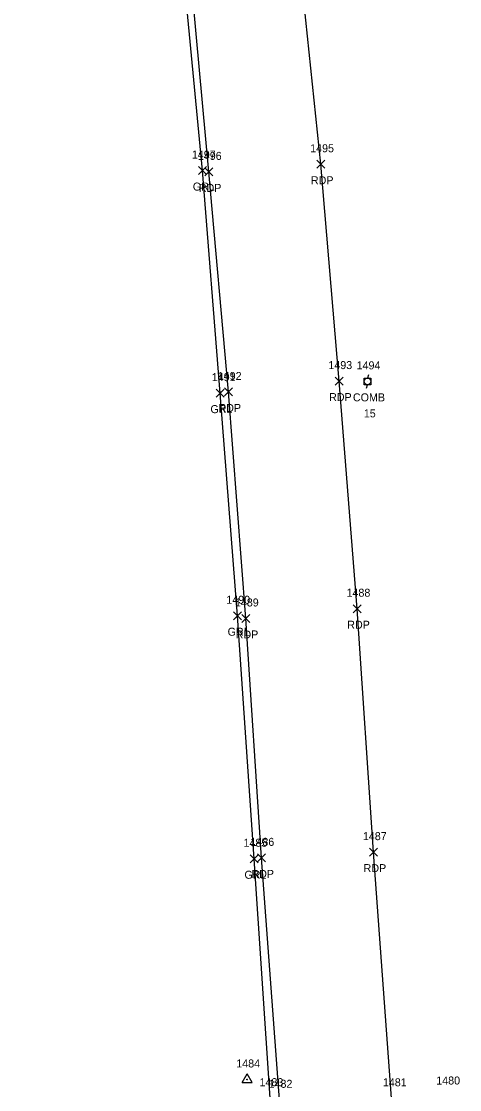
# Model space of a CAD drawing. Extents: x 1503463 to 1505240, y 712171 to 717196.
# Drawn here: x 1503465.6 to 1503575.2, y 716662.1 to 716929.1 of the extents above; entities that cross this region are included whole.
import ezdxf

# ---------------------------------------------------------------- set-up
doc = ezdxf.new("R2010")
doc.units = 0
for name, color, linetype in [('C_I', 7, 'Continuous'), ('CPH', 7, 'Continuous'), ('L_I', 7, 'Continuous'), ('P_A', 7, 'Continuous'), ('P_I', 7, 'Continuous'), ('P_TIC', 7, 'Continuous'), ('PET', 7, 'Continuous'), ('R_A', 7, 'Continuous'), ('R_I', 7, 'Continuous'), ('R_TIC', 7, 'Continuous'), ('RGR', 7, 'Continuous'), ('U_A', 7, 'Continuous'), ('U_C', 7, 'Continuous'), ('U_I', 7, 'Continuous'), ('UP', 7, 'Continuous')]:
    doc.layers.add(name, color=color, linetype=linetype)

msp = doc.modelspace()

# ---------------------------------------------------------------- linework, layer by layer
at = {"layer": 'CPH'}
for p, q in [((1503520.77, 716663.94), (1503522.02, 716666.1)), ((1503523.27, 716663.94), (1503522.02, 716666.1)), ((1503520.77, 716663.94), (1503523.27, 716663.94)), ((1503522.02, 716664.66), (1503522.02, 716664.66))]:
    msp.add_line(p, q, dxfattribs=at)
msp.add_circle((1503522.02, 716664.66), 0.0833, dxfattribs=at)
at = {"layer": 'P_TIC'}
for points in [[(1503539.5, 716892.37), (1503541.5, 716894.37)], [(1503541.5, 716892.37), (1503539.5, 716894.37)], [(1503511.47, 716890.47), (1503513.47, 716892.47)], [(1503513.47, 716890.47), (1503511.47, 716892.47)], [(1503544.06, 716838.19), (1503546.06, 716840.19)], [(1503546.06, 716838.19), (1503544.06, 716840.19)], [(1503516.39, 716835.47), (1503518.39, 716837.47)], [(1503518.39, 716835.47), (1503516.39, 716837.47)], [(1503548.59, 716781.3), (1503550.59, 716783.3)], [(1503550.59, 716781.3), (1503548.59, 716783.3)], [(1503520.69, 716778.87), (1503522.69, 716780.87)], [(1503522.69, 716778.87), (1503520.69, 716780.87)], [(1503524.62, 716719.04), (1503526.62, 716721.04)], [(1503526.62, 716719.04), (1503524.62, 716721.04)], [(1503552.68, 716720.47), (1503554.68, 716722.47)], [(1503554.68, 716720.47), (1503552.68, 716722.47)]]:
    msp.add_lwpolyline(points, dxfattribs=at)
at = {"layer": 'PET'}
for points in [[(1503558.12, 716659.95), (1503553.68, 716721.47), (1503549.59, 716782.3), (1503545.06, 716839.19), (1503540.5, 716893.37), (1503535.09, 716945.45), (1503530.42, 716996.96), (1503523.01, 717048.13), (1503514.13, 717097.79), (1503502.16, 717146.94), (1503490.5, 717186.45)], [(1503530.11, 716659.58), (1503525.62, 716720.04), (1503521.69, 716779.87), (1503517.39, 716836.47), (1503512.47, 716891.47), (1503507.73, 716943.28), (1503502.69, 716992.74), (1503495.94, 717042.95), (1503486.61, 717092.69), (1503475.71, 717138.92), (1503465.59, 717173.85)]]:
    msp.add_lwpolyline(points, dxfattribs=at)
at = {"layer": 'R_TIC'}
for points in [[(1503509.92, 716890.8), (1503511.92, 716892.8)], [(1503511.92, 716890.8), (1503509.92, 716892.8)], [(1503514.33, 716835.18), (1503516.33, 716837.18)], [(1503516.33, 716835.18), (1503514.33, 716837.18)], [(1503518.62, 716779.55), (1503520.62, 716781.55)], [(1503520.62, 716779.55), (1503518.62, 716781.55)], [(1503522.83, 716718.82), (1503524.83, 716720.82)], [(1503524.83, 716718.82), (1503522.83, 716720.82)]]:
    msp.add_lwpolyline(points, dxfattribs=at)
at = {"layer": 'RGR'}
msp.add_lwpolyline([(1503527.84, 716659.98), (1503523.83, 716719.82), (1503519.62, 716780.55), (1503515.33, 716836.18), (1503510.92, 716891.8), (1503505.97, 716943.27), (1503500.58, 716992.89), (1503493.91, 717042.87), (1503484.64, 717092.84), (1503474.7, 717138.79)], dxfattribs=at)
at = {"layer": 'UP'}
for p, q in [((1503551.28, 716838.28), (1503551.28, 716839.95)), ((1503551.28, 716839.95), (1503552.95, 716839.95)), ((1503552.95, 716838.28), (1503551.28, 716838.28)), ((1503551.87, 716837.45), (1503552.12, 716838.28)), ((1503552.37, 716840.78), (1503552.12, 716839.95)), ((1503552.12, 716839.12), (1503552.12, 716839.12)), ((1503552.95, 716839.95), (1503552.95, 716838.28))]:
    msp.add_line(p, q, dxfattribs=at)
msp.add_circle((1503552.12, 716839.12), 0.833, dxfattribs=at)

# ---------------------------------------------------------------- texts
at = {"layer": 'C_I'}
msp.add_text('1484', height=2, dxfattribs=at).set_placement((1503519.33, 716667.66))
at = {"layer": 'L_I'}
msp.add_text('1480', height=2, dxfattribs=at).set_placement((1503569.34, 716663.4))
at = {"layer": 'P_A'}
for p in [(1503537.99, 716888.37), (1503509.96, 716886.47), (1503542.54, 716834.19), (1503514.88, 716831.47), (1503519.18, 716774.87), (1503547.08, 716777.3), (1503551.17, 716716.47), (1503523.11, 716715.04)]:
    msp.add_text('RDP', height=2, dxfattribs=at).set_placement(p)
at = {"layer": 'P_I'}
for s, p in [('1495', (1503537.81, 716896.37)), ('1496', (1503509.72, 716894.47)), ('1493', (1503542.36, 716842.19)), ('1492', (1503514.7, 716839.47)), ('1489', (1503518.99, 716782.87)), ('1488', (1503546.9, 716785.3)), ('1487', (1503550.99, 716724.47)), ('1486', (1503522.87, 716723.04)), ('1481', (1503555.99, 716662.95)), ('1482', (1503527.41, 716662.58))]:
    msp.add_text(s, height=2, dxfattribs=at).set_placement(p)
at = {"layer": 'R_A'}
for p in [(1503508.46, 716886.8), (1503512.87, 716831.18), (1503517.16, 716775.55), (1503521.37, 716714.82)]:
    msp.add_text('GRL', height=2, dxfattribs=at).set_placement(p)
at = {"layer": 'R_I'}
for s, p in [('1497', (1503508.23, 716894.8)), ('1491', (1503513.2, 716839.18)), ('1490', (1503516.84, 716783.55)), ('1485', (1503521.14, 716722.82)), ('1483', (1503525.14, 716662.98))]:
    msp.add_text(s, height=2, dxfattribs=at).set_placement(p)
at = {"layer": 'U_A'}
msp.add_text('COMB', height=2, dxfattribs=at).set_placement((1503548.5, 716834.12))
at = {"layer": 'U_C'}
msp.add_text('15', height=2, dxfattribs=at).set_placement((1503551.22, 716830.12))
at = {"layer": 'U_I'}
msp.add_text('1494', height=2, dxfattribs=at).set_placement((1503549.42, 716842.12))

doc.saveas('drawing.dxf')
